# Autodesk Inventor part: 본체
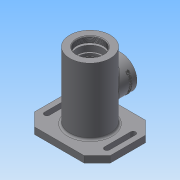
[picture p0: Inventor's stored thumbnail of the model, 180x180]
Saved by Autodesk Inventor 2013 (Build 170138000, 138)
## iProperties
Created: 2017-10
Part Number: 본체
Material: 일반
Document SubType Name: Modeling
Designer: Administrator
Density: 1 g/cm^3
Author: Administrator
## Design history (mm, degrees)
sketch "스케치1"
  geometry: C1 r 31 at (0, 0); 1 further point
  constraints: 1 centre point, 1 coincident
  dimensions: "d0" = 62 diameter of C1
extrude "돌출1" new body sketch "스케치1" distance "d2" = 102; taper "d3" = 0 deg
node "작업 평면1"
sketch "스케치2"
  geometry: L1 (31, 102)-(-31, 102) reference; C1 r 25 at (0, 46); 1 further point
  constraints: 1 centre point, 1 vertical alignment
  dimensions: "d5" = 50 diameter of C1; "d7" = 56 distance from line of L1 C1.centre
extrude "돌출2" join sketch "스케치2" stored distance "d8" = 102; taper "d9" = 0 deg
sketch "스케치3"
  geometry: L1 (-58, -47)-(58, -47); L2 (58, -47)-(58, 47); L3 (58, 47)-(-58, 47); L4 (-58, 47)-(-58, -47); L5 (-58, -47)-(58, 47); L6 (58, -47)-(-58, 47); C1 r 31 at (0, 0) reference
  constraints: 12 end point, 2 midpoint, 2 parallel, 1 horizontal, 1 perpendicular
  dimensions: "d10" = 116 distance of L3.end L2.end; "d11" = 94 distance of L2.end L1.end
extrude "돌출3" join sketch "스케치3" distance "d12" = 10; taper "d13" = 0 deg
chamfer "모따기1" distance "d14" = 20; stored, may be unused: second distance "d15" = 2, angle "d16" = 45 deg
sketch "스케치4"
  geometry: C1 r 35 at (0, 0); 1 further point
  constraints: 1 centre point, 1 coincident
  dimensions: "d17" = 70 diameter of C1
extrude "돌출4" join sketch "스케치4" distance "d19" = 3; taper "d20" = 0 deg
sketch "스케치5"
  geometry: L1 (58, -27)-(58, 27) reference; L2 (42, -20)-(42, 20); L3 (50, 20)-(50, -20); C1 r 35 at (0, 0) reference; A1 r 4 centre (46, 20) between (50, 20) and (42, 20); A2 r 4 centre (46, -20) between (42, -20) and (50, -20); 1 further point
  constraints: 4 end point, 4 point on circle, 3 parallel, 2 centre point, 2 tangent, 1 equal radius, 1 horizontal alignment, 1 midpoint
  dimensions: "d21" = 40 distance of L2.start L2.end; "d22" = 4 radius of A1; "d23" = 46 horizontal distance of C1.centre A2.centre
extrude "돌출5" cut sketch "스케치5" stored distance "d24" = 3; taper "d25" = 0 deg
node "작업 평면2"
sketch "스케치6"
  geometry: L1 (31, 102)-(-31, 102) reference; L2 (47, 71)-(47, 21) reference; 2 further points
  constraints: 1 other
  dimensions: "d27" = 56 distance from line of L1 point (37, 46); "d28" = 10 distance from line of L2 point (37, 46)
feature "엠보싱1" sketch "스케치6" dims "d0" = 62, "d29" = 0.5, "d30" = 0
sketch "스케치7"
  geometry: C1 r 31 at (0, 0) reference
hole "구멍1" sketch "스케치7" at (0, 0) diameter "d31" = 40.376; stored, may be unused: countersink angle "d35" = 90 deg, drill point angle "d37" = 0 deg; dims "d32" = 6, "d33" = 4, "d34" = 2, "d36" = 9
sketch "스케치8"
  geometry: C1 r 20.188 at (0, 0) reference; C2 r 24 at (0, 0)
  constraints: 1 centre point, 1 coincident
  dimensions: "d38" = 48 diameter of C2
extrude "돌출6" cut sketch "스케치8" distance "d40" = 3; taper "d41" = 0 deg
sketch "스케치9"
  geometry: C1 r 24 at (0, 0) reference; C2 r 20 at (0, 0)
  constraints: 1 centre point, 1 coincident
  dimensions: "d43" = 40 diameter of C2
extrude "돌출7" cut sketch "스케치9" distance "d45" = 9; taper "d46" = 0 deg
sketch "스케치10"
  geometry: C1 r 20 at (0, 0) reference; C2 r 17.5 at (0, 0)
  constraints: 1 centre point, 1 coincident
  dimensions: "d47" = 35 diameter of C2
extrude "돌출8" cut sketch "스케치10" distance "d49" = 3.25; taper "d50" = 0 deg
sketch "스케치11"
  geometry: C1 r 17.5 at (0, 0) reference; C2 r 18.5 at (0, 0)
  constraints: 1 centre point, 1 coincident
  dimensions: "d51" = 37 diameter of C2
extrude "돌출9" cut sketch "스케치11" distance "d53" = 1.75; taper "d54" = 0 deg
sketch "스케치12"
  geometry: C1 r 18.5 at (0, 0) reference; C2 r 17.5 at (0, 0)
  constraints: 1 centre point, 1 coincident
  dimensions: "d55" = 35 diameter of C2
extrude "돌출10" cut sketch "스케치12" distance "d57" = 11; taper "d58" = 0 deg
sketch "스케치13"
  geometry: C1 r 17.5 at (0, 0) reference; C2 r 26 at (0, 0)
  constraints: 1 centre point, 1 coincident
  dimensions: "d59" = 52 diameter of C2
extrude "돌출11" cut sketch "스케치13" distance "d61" = 38; taper "d62" = 0 deg
sketch "스케치14"
  geometry: C1 r 26 at (0, 0) reference; C2 r 17.5 at (0, 0)
  constraints: 1 centre point, 1 coincident
  dimensions: "d63" = 35 diameter of C2
extrude "돌출12" cut sketch "스케치14" distance "d65" = 11; taper "d66" = 0 deg
sketch "스케치15"
  geometry: C1 r 17.5 at (0, 0) reference; C2 r 16.5 at (0, 0)
  constraints: 1 centre point, 1 coincident
  dimensions: "d67" = 33 diameter of C2
extrude "돌출13" cut sketch "스케치15" distance "d69" = 5; taper "d70" = 0 deg
sketch "스케치16"
  geometry: C1 r 16.5 at (0, 0) reference; C2 r 10 at (0, 0)
  constraints: 1 centre point, 1 coincident
  dimensions: "d71" = 20 diameter of C2
extrude "돌출14" cut sketch "스케치16" distance "d73" = 2.7; taper "d74" = 0 deg
sketch "스케치17"
  geometry: C1 r 10 at (0, 0) reference; C2 r 12.5 at (0, 0)
  constraints: 1 centre point, 1 coincident
  dimensions: "d75" = 25 diameter of C2
extrude "돌출15" cut sketch "스케치17" distance "d77" = 7.3; taper "d78" = 0 deg
sketch "스케치18"
  geometry: L1 (-12.5, 1)-(12.5, 1) reference; L2 (-35, -13)-(35, -13) reference; L3 (0, 1)-(16, 1); L4 (0, 1)-(0, -13); L5 (0, -13)-(22, -13); L6 (22, -13)-(16, 1); 1 further point
  constraints: 8 end point, 2 midpoint, 2 point on line
  dimensions: "d79" = 16 distance of L3.start L3.end; "d80" = 14 distance of L3.start L4.end; "d82" = 22 distance of L4.end L5.end
revolve "회전1" sketch "스케치18" stored, may be unused: angle "d83" = 90 deg
sketch "스케치19"
  geometry: C1 r 25 at (0, 0) reference; C2 r 16 at (0, 0); 1 further point
  constraints: 1 centre point, 1 coincident
  dimensions: "d84" = 32 diameter of C2
extrude "돌출16" cut sketch "스케치19" distance "d86" = 47; taper "d87" = 0 deg
sketch "스케치20"
  geometry: L1 (0, 0)-(-20.5, 0); L2 (0, 0)-(20.5, 0); C1 r 25 at (0, 0) reference; 1 further point
  constraints: 4 end point, 1 collinear, 1 horizontal
  dimensions: "d89" = 20.5 distance of L1.start L1.end; "d90" = 20.5 distance of L1.start L2.end
hole "구멍2" sketch "스케치20" at (-20.5, 0), (20.5, 0) diameter "d91" = 2.459; stored, may be unused: countersink angle "d95" = 90 deg, drill point angle "d97" = 118 deg; dims "d92" = 6, "d93" = 4, "d94" = 2, "d96" = 8
fillet "모깎기1" dims "d98" = 3
chamfer "모따기2" distance "d99" = 1; stored, may be unused: second distance "d100" = 2, angle "d101" = 45 deg
fillet "모깎기2" dims "d102" = 3
chamfer "모따기3" distance "d103" = 1; stored, may be unused: second distance "d104" = 2, angle "d105" = 45 deg
fillet "모깎기3" dims "d106" = 3
chamfer "모따기4" distance "d107" = 0.7; stored, may be unused: second distance "d108" = 2, angle "d109" = 30 deg
fillet "모깎기4" dims "d110" = 0.3
fillet "모깎기5" dims "d111" = 3
fillet "모깎기6" dims "d112" = 0.3
chamfer "모따기5" distance "d113" = 1; stored, may be unused: second distance "d114" = 2, angle "d115" = 30 deg
node "솔리드1"
mirror "대칭1"
other parameters: "d4" = 47
